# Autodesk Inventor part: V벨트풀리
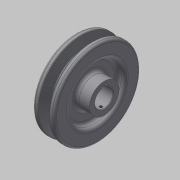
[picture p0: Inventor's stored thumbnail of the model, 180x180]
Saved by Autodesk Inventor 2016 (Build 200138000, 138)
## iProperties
Created: 2015-11
Part Number: V벨트풀리
Material: 강철, 탄소
Document SubType Name: Modeling
Designer: mduedu
Density: 7.87 g/cm^3
Appearance: 기본값
Mass: 425.414 g
Surface Area: 185.664 cm^2
Volume: 54.0551 cm^3
Author: mduedu
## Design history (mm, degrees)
sketch "스케치1"
  geometry: L1 (-9.5, 0)-(9.5, 0); L2 (0, 0)-(0, 37.7); L3 (-4.825, 37.7)-(-9.5, 37.7); L4 (-9.5, 37.7)-(-9.5, 0); L5 (0, 28.7)-(-2.074, 28.7); L6 (-2.074, 28.7)-(-4.825, 37.7); L7 (4.825, 37.7)-(9.5, 37.7); L8 (9.5, 37.7)-(9.5, 0); L9 (0, 28.7)-(2.074, 28.7); L10 (2.074, 28.7)-(4.825, 37.7); L11 (-9.5, 35)-(9.5, 35); 3 further points
  constraints: 22 end point, 7 point on line, 4 perpendicular, 3 symmetric about line, 1 coincident, 1 horizontal, 1 horizontal alignment, 1 midpoint, 1 vertical
  dimensions: "d0" = 19 distance of L1.start L1.end; "d2" = 75.4 diameter of L2.end L1 (derived); "d3" = 34 deg angle of L10 L6; "d4" = 6.3 distance between parallel lines of L11 L9; "d5" = 2.7 distance between parallel lines of L7 L11; "d6" = 8 distance of point (4, 35) point (-4, 35); "d7" = 70 diameter of L11 L1
revolve "회전1" sketch "스케치1" stored, may be unused: angle "d8" = 90 deg
sketch "스케치2"
  geometry: C1 r 24 at (0, 0); C2 r 13 at (0, 0); 1 further point
  constraints: 2 centre point, 2 coincident
  dimensions: "d9" = 48 diameter of C1; "d10" = 26 diameter of C2
extrude "돌출1" cut sketch "스케치2" distance "d11" = 6; taper "d12" = 0 deg
extrude "돌출3" join sketch "스케치2" distance "d37" = 6; taper "d38" = 0 deg
fillet "모깎기1" dims "d13" = 3
fillet "모깎기2" dims "d14" = 3
fillet "모깎기3" dims "d15" = 1, "d16" = 0.5, "d17" = 2
hole "구멍1" diameter "d20" = 16; stored, may be unused: countersink angle "d24" = 90 deg, drill point angle "d26" = 118 deg; dims "d21" = 6, "d22" = 4, "d23" = 2, "d25" = 8, "d53" = 10, "d54" = 10
sketch "스케치3"
  geometry: L1 (-2.5, 0)-(2.5, 0); L2 (2.5, 0)-(2.5, 10.3); L3 (2.5, 10.3)-(-2.5, 10.3); L4 (-2.5, 10.3)-(-2.5, 0); 2 further points
  constraints: 8 end point, 2 parallel, 1 coincident, 1 horizontal, 1 midpoint, 1 perpendicular
  dimensions: "d27" = 5 distance of L2.end L3.end; "d29" = 10.3 distance of L3.end L1.start
extrude "돌출2" cut sketch "스케치3" stored distance "d30" = 6; taper "d31" = 0 deg
node "작업 평면1"
sketch "스케치4"
  geometry: L1 (19, -27)-(19, 27) reference; 2 further points
  constraints: 1 horizontal alignment
  dimensions: "d52" = 22 distance from line of L1 point (-3, 0)
hole "구멍2" sketch "스케치4" at (-3, 0) diameter "d42" = 2.459; stored, may be unused: countersink angle "d46" = 90 deg, drill point angle "d48" = 118 deg; dims "d43" = 6, "d44" = 4, "d45" = 2, "d47" = 8
chamfer "모따기3" distance "d58" = 0.5; stored, may be unused: second distance "d59" = 2, angle "d60" = 45 deg
node "솔리드1"
mirror "대칭1"
